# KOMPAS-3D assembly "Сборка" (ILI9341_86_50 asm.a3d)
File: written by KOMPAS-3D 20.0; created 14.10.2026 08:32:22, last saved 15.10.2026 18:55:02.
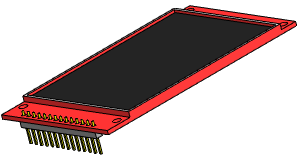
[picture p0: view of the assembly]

Document properties: Полное имя файла: D:\myProjects\Progect_esp32\box_compas\монитор\ILI9341_86_50 asm.a3d

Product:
- Part/product: Сборка
    Масса: 0.0808946
  - Component [detail]: Деталь  | Масса: 0.0790697; source file: ILI9341_86_50.m3d
  - Component [detail]: Деталь  | Масса: 0.00182492; source file: ..\разъемы\pls_14.m3d

Referenced files in D:\myProjects\Progect_esp32\box_compas\монитор\: ILI9341_86_50.m3d
Referenced files in D:\myProjects\Progect_esp32\box_compas\разъемы\: pls_14.m3d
